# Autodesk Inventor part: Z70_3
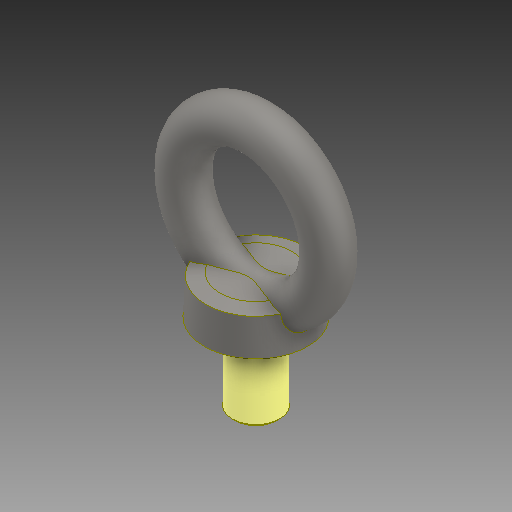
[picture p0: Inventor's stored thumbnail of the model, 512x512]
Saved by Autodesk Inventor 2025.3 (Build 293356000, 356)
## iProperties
Created: 2025-03
Part Number: Z70_3
Material: Všeobecné
Document SubType Name: Modeling
Designer: Patrik
Density: 1 g/cm^3
Appearance: Výchozí
Mass: 36.3806 g
Surface Area: 96.6677 cm^2
Volume: 36.3806 cm^3
Author: Patrik
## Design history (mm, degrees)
feature "Base1"
node "Těleso1"
